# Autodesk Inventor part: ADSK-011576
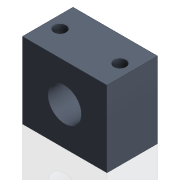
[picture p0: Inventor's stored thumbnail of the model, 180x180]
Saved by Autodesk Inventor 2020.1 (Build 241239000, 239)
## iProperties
Created: 2000-02
Part Number: ADSK-011576
Document SubType Name: Modeling
Description: PLT-03,SN,CP,15,025,022,655,SHAFT BEARING
Designer: sspink
Material: Pearson Nylatron
Density: 1.13867 g/cm^3
Appearance: Nylatron
Mass: 127.116 g
Surface Area: 213.686 cm^2
Volume: 111.635 cm^3
Control State: 0
Checked Out: False
Master: False
Shininess: 10.0
Length Units: 11269
Angle Units: 11279
Time Units: 11290
Mass Units: 11283
Length Display Precision: 3
Angle Display Precision: 2
Compacted: True
Cutlength: 2.50x2.25 (5.63 SI)
Material_Number: A102223
Material Desc: SHEET,NYLATRON,1.500
Dimensions: 57x38x63,5 mm
Mass: 0,127 kg
VLT_Material: Pearson Nylatron
Density: 1.13867
Volumn: 129.93313563508178
Area: 236.7612941972467
PropertySet Name: Model Information
Author: sspink
Revision Number: -
Title: PLT-03,SN,CP,15,025,022,655,SHAFT BEARING
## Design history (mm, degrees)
node "Extrusion1" dims "d2" = 38, "d3" = 0
  sketch "Sketch1"
    geometry: L1 (0, 0)-(63.5, 0); L2 (63.5, 0)-(63.5, 57); L3 (63.5, 57)-(0, 57); L4 (0, 57)-(0, 0)
    constraints: 8 end point, 2 parallel, 1 horizontal, 1 perpendicular
    dimensions: "d0" = 63.5 distance between parallel lines of L2 L4; "d1" = 57 distance between parallel lines of L1 L3
node "Extrusion2" dims "d5" = 25.4, "d6" = 0
  sketch "Sketch2"
    geometry: L1 (0, 0)-(0, 57) reference; L2 (63.5, 0)-(0, 0) reference; L3 (63.5, 57)-(63.5, 0) reference; L4 (0, 57)-(63.5, 57) reference; L5 (0, 28.5)-(63.5, 28.5); L6 (31.75, 57)-(31.75, 0); C1 r 12.5 at (31.75, 28.5)
    constraints: 5 midpoint, 4 end point, 1 centre point
    dimensions: "d4" = 25 diameter of C1
node "Hole1" dims "d9" = 9, "d10" = 9.525, "d11" = 6.35, "d12" = 60 deg, "d13" = 19.05, "d14" = 118 deg, "d16" = 6
  sketch "Sketch3"
    geometry: L1 (0, 0)-(0, -38) reference; L2 (9.25, -19)-(54.25, -19); L3 (0, -38)-(63.5, -38) reference; 3 further points
    constraints: 3 midpoint, 2 end point, 1 horizontal, 1 horizontal alignment, 1 vertical alignment
    dimensions: "d15" = 45 distance of L2.end L2.start
node "Solide1"
node "Corps solides"
node "Corps surfaciques"
